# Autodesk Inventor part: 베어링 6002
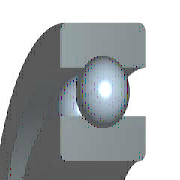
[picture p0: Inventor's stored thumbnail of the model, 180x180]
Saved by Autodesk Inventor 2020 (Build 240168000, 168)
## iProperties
Created: 2012-02
Part Number: 베어링 6002
Material: 알루미늄 6061
Description: 깊은 그루브 볼 베어링
Document SubType Name: Modeling
Standard: KS B 2023
Designer: mduedu
Standards Organization: KS
Language: ko-KR
Size Designation: 6002 - 15 x 32 x 9
Categories: <MemberInstance><Categories><Category DisplayName="샤프트 부품" InternalName="7f7aeb1f-a693-4053-b835-cee3144e0d98" Mnemonic="SHFT"><Category DisplayName="베어링" Inter
Density: 2.7 g/cm^3
Mass: 10.2409 g
Surface Area: 39.9079 cm^2
Volume: 3.79292 cm^3
Appearance: 분홍색
IsCustomPart: 1
Author: mduedu
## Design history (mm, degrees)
sketch "스케치" dims "d0" = 4.42 (= -0.26 x WD + 0.26 x BD)
  geometry: L1 (2.29, 11.75)-(6.71, 11.75); L2 (4.5, 11.75)-(4.5, 9.54); L3 (4.5, 11.75)-(4.5, 13.96); L4 (2.858, 10.271)-(0, 10.271); L5 (0, 7.5)-(9, 7.5); L6 (2.858, 13.229)-(0, 13.229); L7 (0, 16)-(9, 16); L8 (9, 7.5)-(9, 10.271); L9 (6.142, 10.271)-(9, 10.271); L10 (6.142, 13.229)-(9, 13.229); L11 (9, 16)-(9, 13.229); L12 (-1.4, 0)-(8.4, 0) reference; L13 (0, -0.3)-(0, 5.3) reference
  constraints: 22 end point, 4 point on line, 2 collinear, 2 perpendicular, 2 symmetric about line, 1 midpoint, 1 parallel, 14 other
  dimensions: "d9" = 15 diameter of L5 L12 (= WD); "d11" = 32 diameter of L7 L12 (= BD); "d12" = 9 distance between parallel lines of L8 L13 (= KB); "d13" = 20.542 diameter of L9 L12 (= 0.326 x BD + 0.674 x WD)
revolve "본체" stored, may be unused: angle "d6" = 90 deg
revolve "볼" stored, may be unused: angle "d7" = 90 deg
pattern_circular "IDS_ARRAYBALL[SIMPL:T]" dims angle "d3" = 360 deg
body "Solid1"
fillet "모깎기1" dims "d1" = 0.3 (= KRS)
other parameters: "WD" = 15 [user parameter; used in 5 equation terms], "BD" = 32 [user parameter; used in 5 equation terms], "KB" = 9 [user parameter; used in 1 equation term], "KRS" = 0.3 [user parameter; used in 1 equation term], "d4" = 0, "d5" = 0, "d8" = 0, "d14" = 0, "d15" = 0, "BBA" = 0 [user parameter], "BC0" = 2850000 [user parameter], "BC" = 5590000 [user parameter], "BR" = 16 (= 0.5 x BD) [user parameter], "WR" = 7.5 (= 0.5 x WD) [user parameter]
